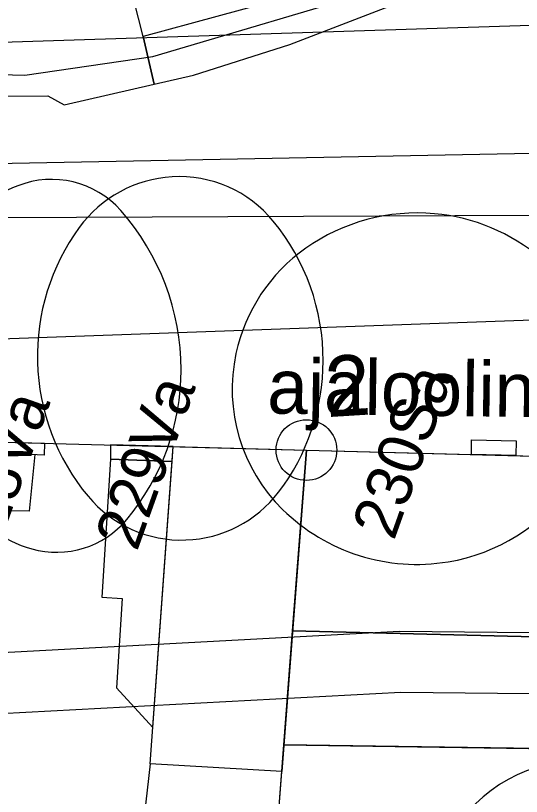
# Model space of a CAD drawing. Extents: x 738423 to 738903, y 6589762 to 6590172.
# Drawn here: x 738661.32 to 738678, y 6589928.62 to 6589954.37 of the extents above; entities that cross this region are included whole.
import ezdxf

# ---------------------------------------------------------------- set-up
doc = ezdxf.new("R2010")
doc.units = 0
for name, color, linetype in [('_1927_hoonestus', 7, 'Continuous'), ('_1927_katuse_kalded', 7, 'Continuous'), ('_1927_koordin_punktid_nr', 7, 'Continuous'), ('_1927_krundi_piir', 7, 'Continuous'), ('_1927_uhepoolne_katusekalle', 7, 'Continuous'), ('_ajalooline_liivavall_linnamuur', 7, 'Continuous'), ('a_dendro_II_Vkl_puu', 7, 'Continuous'), ('a_dendro_III_vk_puu', 7, 'Continuous'), ('a_dendro_puu_nr', 7, 'Continuous'), ('Default', 7, 'Continuous'), ('plan_ala', 7, 'Continuous'), ('v_dp_jalak_liikumine', 7, 'Continuous'), ('v_olol_kitsendus_tehnov', 7, 'Continuous'), ('v_olol_transp_jjt_jalg', 7, 'Continuous'), ('v_olol_transp_tee', 7, 'Continuous'), ('v_vormistus_tekst', 7, 'Continuous')]:
    doc.layers.add(name, color=color, linetype=linetype)

# ---------------------------------------------------------------- blocks, each defined once
blk = doc.blocks.new('_U676')
at = {"layer": 'Default'}
for centre, radius, start, end in [((0.0013323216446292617, -0.011065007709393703), 0.01717769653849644, 96.18195829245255, 125.09681027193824), ((0.0013531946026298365, -0.011257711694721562), 0.017371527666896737, 67.84269756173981, 96.18195829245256), ((0.00487309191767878, -0.0026140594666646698), 0.008038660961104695, 25.660167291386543, 67.84269756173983), ((-0.004077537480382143, -0.003366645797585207), 0.007768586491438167, 125.09681027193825, 168.68173119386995), ((0.0066277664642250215, -0.00177109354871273), 0.0060920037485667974, 315.85637789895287, 25.66016729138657), ((-0.005765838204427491, -0.0030287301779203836), 0.006046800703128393, 168.68173119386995, 234.48463763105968), ((-0.0003586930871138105, 0.005009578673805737), 0.015827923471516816, 274.27278411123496, 315.85637789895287), ((-0.00032744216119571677, 0.004591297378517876), 0.015408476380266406, 234.48463763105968, 274.27278411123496)]:
    blk.add_arc(centre, radius, start, end, dxfattribs=at)
blk = doc.blocks.new('_U677')
at = {"layer": 'Default'}
for centre, radius, start, end in [((0.0007182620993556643, -0.005510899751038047), 0.014388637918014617, 95.76795668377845, 134.15082210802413), ((0.0007257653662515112, -0.005585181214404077), 0.01446329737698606, 58.28829486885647, 95.76795668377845), ((0.0040490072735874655, -0.00020685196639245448), 0.00814108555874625, 7.5792940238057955, 58.28829486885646), ((-0.0037035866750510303, -0.0009559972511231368), 0.008040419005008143, 134.15082210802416, 186.32642093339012), ((0.004152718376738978, -0.00019305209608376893), 0.008036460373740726, 313.67137384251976, 7.579294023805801), ((-0.0036988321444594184, -0.000955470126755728), 0.008045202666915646, 186.3264209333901, 236.85170050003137), ((-0.00030542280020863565, 0.004476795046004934), 0.014492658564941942, 274.2177760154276, 313.67137384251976), ((-0.00028976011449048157, 0.004264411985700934), 0.014279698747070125, 236.8517005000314, 274.2177760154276)]:
    blk.add_arc(centre, radius, start, end, dxfattribs=at)
blk = doc.blocks.new('_U678')
at = {"layer": 'Default'}
for centre, radius, start, end in [((-0.002579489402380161, 0.001985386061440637), 0.01111431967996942, 82.0551215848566, 139.83879613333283), ((-0.002626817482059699, 0.001646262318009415), 0.011456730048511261, 39.469554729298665, 82.05512158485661), ((-0.0014216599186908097, 0.0010082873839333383), 0.012629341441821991, 139.83879613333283, 193.7438684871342), ((-0.0036379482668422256, 0.0008136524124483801), 0.012766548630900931, 359.2278417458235, 39.46955472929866), ((-0.003454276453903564, 0.0008111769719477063), 0.012582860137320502, 323.95832458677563, 359.2278417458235), ((-0.0016596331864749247, 0.0009500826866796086), 0.012384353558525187, 193.74386848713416, 238.8156217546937), ((-0.0024338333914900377, 6.864704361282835e-05), 0.01132085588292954, 286.7065177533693, 323.95832458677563), ((-0.002354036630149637, -0.00019721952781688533), 0.011043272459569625, 238.81562175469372, 286.7065177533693)]:
    blk.add_arc(centre, radius, start, end, dxfattribs=at)
blk = doc.blocks.new('_U688')
at = {"layer": 'Default'}
for centre, radius, start, end in [((0.002276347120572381, 0.001824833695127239), 0.011651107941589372, 49.162226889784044, 106.55395243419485), ((0.0021298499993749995, 0.002317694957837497), 0.011136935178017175, 106.55395243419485, 155.37187784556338), ((0.0035985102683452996, 0.0033545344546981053), 0.009629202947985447, 345.3983052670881, 49.162226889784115), ((0.0006497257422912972, 0.002996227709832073), 0.009508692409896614, 155.37187784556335, 208.50422751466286), ((0.0028839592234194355, 0.00354068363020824), 0.010367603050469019, 302.57956319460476, 345.3983052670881), ((0.001212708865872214, 0.003301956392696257), 0.010149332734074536, 208.50422751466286, 236.55502715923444), ((0.001969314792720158, 0.0044474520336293), 0.011522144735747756, 236.5550271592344, 262.8497923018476), ((0.0020243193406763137, 0.0048859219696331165), 0.011964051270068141, 262.84979230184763, 302.5795631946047)]:
    blk.add_arc(centre, radius, start, end, dxfattribs=at)

msp = doc.modelspace()

# ---------------------------------------------------------------- linework, layer by layer
at = {"layer": '_1927_hoonestus'}
for points in [[(738659.7860125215, 6589940.3357087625), (738662.2758304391, 6589940.27018861), (738662.2654888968, 6589939.877201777), (738659.7471452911, 6589939.993841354)], [(738676.3507655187, 6589939.898946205), (738676.3507655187, 6589940.3782356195), (738677.8272607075, 6589940.348590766), (738677.8165006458, 6589939.86014418)], [(738659.747145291, 6589939.993841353), (738661.9526274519, 6589939.891692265), (738661.7639830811, 6589938.0275368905), (738659.5258756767, 6589938.047603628)], [(738664.4502403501, 6589940.212968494), (738664.4502403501, 6589939.739661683), (738666.4852975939, 6589939.6632169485), (738666.5214077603, 6589940.158465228)], [(738670.9087498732, 6589940.043011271), (738670.0996569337, 6589929.448830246), (738665.758297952, 6589929.692470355), (738666.5214077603, 6589940.158465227)], [(738670.9087498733, 6589940.043011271), (738679.7282311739, 6589939.8095354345), (738678.0506429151, 6589918.541122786), (738669.2749026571, 6589918.640213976), (738669.5947892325, 6589922.838186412)], [(738664.4502403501, 6589939.739661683), (738664.1695733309, 6589935.190384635), (738664.8325317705, 6589935.149483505), (738664.6505858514, 6589932.200357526), (738665.8457990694, 6589930.892541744), (738666.4852975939, 6589939.6632169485)], [(738665.758297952, 6589929.692470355), (738665.459647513, 6589927.08831797), (738656.5091354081, 6589928.314041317), (738656.3355450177, 6589927.0464446), (738654.8545915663, 6589927.249253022), (738654.4566176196, 6589924.9626378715), (738669.5947892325, 6589922.838186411), (738670.0996549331, 6589929.448830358)]]:
    msp.add_lwpolyline(points, close=True, dxfattribs=at)
at = {"layer": '_1927_katuse_kalded'}
for points in [[(738703.6658553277, 6589939.175840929), (738697.9292015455, 6589933.403840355), (738670.4536419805, 6589934.083874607), (738670.9086865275, 6589940.042181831)], [(738697.9292015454, 6589933.403840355), (738693.6272828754, 6589929.981278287), (738670.1667035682, 6589930.326732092), (738670.4536419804, 6589934.083874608)]]:
    msp.add_lwpolyline(points, close=True, dxfattribs=at)
at = {"layer": '_1927_koordin_punktid_nr'}
msp.add_circle((738670.908755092, 6589940.043011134), 0.9999999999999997, dxfattribs=at)
at = {"layer": '_1927_krundi_piir'}
msp.add_lwpolyline([(738649.2135835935, 6589949.273370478), (738690.9043289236, 6589950.074278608), (738685.5858837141, 6589972.9080395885), (738646.6848373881, 6589968.012491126)], close=True, dxfattribs=at)
msp.add_lwpolyline([(738642.9591139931, 6589940.778512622), (738670.908755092, 6589940.043011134), (738703.6658553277, 6589939.175840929), (738699.2597677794, 6589917.23983417), (738689.9894215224, 6589918.406316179), (738669.274902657, 6589918.640213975), (738669.45830989, 6589921.006172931), (738669.5947892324, 6589922.838186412), (738670.908755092, 6589940.043011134)], dxfattribs=at)
at = {"layer": '_1927_uhepoolne_katusekalle'}
for points in [[(738666.5214077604, 6589940.158465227), (738670.9087498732, 6589940.04301127), (738670.0996569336, 6589929.448830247), (738665.758297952, 6589929.692470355)], [(738670.1667035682, 6589930.326732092), (738678.9700315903, 6589930.197104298), (738678.0506429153, 6589918.541122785), (738669.2749026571, 6589918.640213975)]]:
    msp.add_lwpolyline(points, close=True, dxfattribs=at)
at = {"layer": '_ajalooline_liivavall_linnamuur'}
msp.add_lwpolyline([(738708.289405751, 6589968.14747116), (738780.2257645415, 6589985.561122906), (738769.667506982, 6589952.525563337), (738767.8196994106, 6589945.734830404), (738713.208654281, 6589947.930212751), (738615.9368314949, 6589947.498858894), (738617.4577657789, 6589962.743100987), (738623.554579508, 6589962.319832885), (738622.8971321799, 6589952.276700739), (738711.4568073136, 6589955.13)], close=True, dxfattribs=at)
at = {"layer": 'plan_ala'}
msp.add_lwpolyline([(738772.2221966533, 6589837.873120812), (738583.11, 6589865.669999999), (738583.11, 6589865.669999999), (738577.13, 6589865.85), (738565.7035831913, 6589866.139410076), (738565.4500000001, 6589885.77), (738564.4932191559, 6589941.052825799), (738581.9, 6589941.1499999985), (738615.11, 6589942.169999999), (738650.0499999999, 6589943.319999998), (738691.2690631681, 6589944.800325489), (738696.0901513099, 6589944.851371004), (738713.89, 6589945.129999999), (738703.51, 6589987.789999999), (738752.8799999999, 6590000.39), (738783.1408503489, 6590007.463828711), (738767.5688789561, 6589951.87996157)], close=True, dxfattribs=at)
at = {"layer": 'v_dp_jalak_liikumine'}
msp.add_lwpolyline([(738578.970251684, 6589937.862152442), (738584.5045426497, 6589940.144760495), (738605.4024666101, 6589943.568672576), (738625.3859761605, 6589947.878936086), (738640.1312149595, 6589950.743854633), (738648.7056120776, 6589951.738200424), (738653.8672730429, 6589953.473473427), (738655.5881166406, 6589952.565697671), (738661.6250098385, 6589952.40725923), (738665.8485456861, 6589953.015650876), (738673.5708121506, 6589955.317894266), (738678.5915111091, 6589956.996715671), (738685.859941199, 6589956.947013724), (738690.3670481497, 6589963.134599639), (738692.7749703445, 6589968.674602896), (738694.4616114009, 6589968.262260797), (738695.9325192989, 6589968.635332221), (738697.285754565, 6589969.852723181), (738697.4340711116, 6589971.167063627), (738697.1595016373, 6589972.894973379), (738696.0808358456, 6589974.465800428), (738695.1786790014, 6589976.311522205), (738693.4626197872, 6589985.738938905), (738690.6242451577, 6589995.688458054)], dxfattribs=at)
at = {"layer": 'v_olol_kitsendus_tehnov'}
msp.add_lwpolyline([(738657.5236514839, 6589931.178043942), (738674.0238867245, 6589932.064447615), (738684.6483694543, 6589931.951173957), (738696.3015328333, 6589931.3201832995), (738702.5245470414, 6589932.39569243), (738701.1625300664, 6589944.936942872), (738699.154078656, 6589944.9064775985), (738700.3334863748, 6589934.046666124), (738696.1838115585, 6589933.329487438), (738684.713129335, 6589933.950597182), (738673.980859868, 6589934.065020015), (738656.984348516, 6589933.151956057)], dxfattribs=at)
at = {"layer": 'v_olol_transp_jjt_jalg'}
msp.add_lwpolyline([(738670.3810673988, 6589955.011420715), (738665.531, 6589953.682000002), (738665.8846800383, 6589952.109225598), (738667.1904830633, 6589952.408191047), (738670.3620813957, 6589953.413175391), (738674.7894283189, 6589955.128399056)], dxfattribs=at)
at = {"layer": 'v_olol_transp_tee'}
msp.add_lwpolyline([(738646.3832984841, 6589964.037390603), (738647.3529999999, 6589960.153), (738648.081525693, 6589957.532351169), (738651.1440000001, 6589958.355), (738651.5140000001, 6589956.821), (738648.4800000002, 6589956.006000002), (738649.6690000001, 6589951.143999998), (738654.7599999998, 6589952.5320000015), (738655.04, 6589951.6669999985), (738662.3799999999, 6589951.723000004), (738662.9180000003, 6589951.430000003), (738665.8846800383, 6589952.109225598), (738665.5310000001, 6589953.682000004), (738663.0032944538, 6589963.626310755), (738651.8771274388, 6589963.901505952)], close=True, dxfattribs=at)

# ---------------------------------------------------------------- block references
at = {"layer": 'a_dendro_II_Vkl_puu', "xscale": 500.0000000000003, "yscale": 500.0000000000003, "rotation": 85.69234851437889}
msp.add_blockref('_U678', (738675.105, 6589943.26), dxfattribs=at)
at = {"layer": 'a_dendro_III_vk_puu', "xscale": 500.0000000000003, "yscale": 500.0000000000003, "rotation": 85.69234851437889}
for name, p in [('_U676', (738661.374, 6589942.683000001)), ('_U677', (738666.4589999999, 6589942.978)), ('_U688', (738681.4149999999, 6589923.042999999))]:
    msp.add_blockref(name, p, dxfattribs=at)

# ---------------------------------------------------------------- texts
at = {"layer": '_1927_koordin_punktid_nr'}
msp.add_text('2', height=1.9999999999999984, rotation=3.560863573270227, dxfattribs=at).set_placement((738671.5864558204, 6589941.126459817))
at = {"layer": 'a_dendro_puu_nr'}
for s, p in [('230Sa', (738673.7924876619, 6589937.02904657)), ('229Va', (738665.3196273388, 6589936.669903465)), ('228Va', (738660.525058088, 6589936.157954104))]:
    msp.add_text(s, height=1.4999999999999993, rotation=70.36105075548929, dxfattribs=at).set_placement(p)
at = {"layer": 'v_vormistus_tekst'}
msp.add_text('ajalooline Vahe tänav', height=1.7999999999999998, rotation=359.20505069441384, dxfattribs=at).set_placement((738669.6088702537, 6589941.249649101))

doc.saveas('drawing.dxf')
